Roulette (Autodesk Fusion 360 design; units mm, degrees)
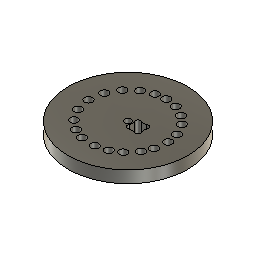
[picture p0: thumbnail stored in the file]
parameter "Diam" = 150
parameter "Length_Z" = 15
parameter "Diameter" = 10
parameter "Higth" = 15
parameter "Ss" = 15 (= "Diameter * 1.5")
parameter "Circumcircle_R" = 47.9434 (= "Ss / ( 2 * sin(( 180 / n ) * 1 deg) )")
parameter "HLZ" = 7.5 (= "Length_Z / 2")
parameter "Middle_Bar_Diam" = 8
sketch "Sketch1" plane through (0, 0, 0) normal (0, 0, 1) x axis (1, 0, 0)
  circle C1 centre (0, 0) radius 75
  point P1 (0, 0)
  point P2 (0, 0)
  coincident P1 P2
  dimension "d3" diameter C1 = 150 (= "Diam")
extrude "Extrude1" new body sketch "Sketch1" along normal blind 15 (= "Length_Z")
sketch "Sketch1" plane through (0, 0, 0) normal (0, 0, 1) x axis (1, 0, 0)
  circle C1 centre (0, 47.9434) radius 5
  point P1 (0, 0)
  point P2 (0, 47.9434)
  vertical P1 P2
  dimension "d7_1" diameter C1 = 10 (= "Diameter")
  dimension "d12" distance P1 P2 = 47.9434 (= "Circumcircle_R")
extrude "Extrude1" new body sketch "Sketch1" along normal blind 15 (= "Higth")
circular_pattern "C-Pattern1" TotalAngle 360 named "d4_1"
sketch "Sketch2" plane through (0, 0, 0) normal (0, 0, 1) x axis (1, 0, 0)
  circle C1 centre (0, 0) radius 5
  point P1 (0, 0)
  point P2 (0, 0)
  coincident P1 P2
  dimension "d13" diameter C1 = 10 (= "Diameter")
extrude "Extrude2" new body sketch "Sketch2" along normal blind 15 (= "Higth")
joint "Assemble1" alignAngle 0 alignOffsetX 0 alignOffsetY 0
combine "Combine2"
copy_paste "CopyPaste1"
combine "Combine3"
copy_paste "CopyPaste2"
combine "Combine4"
copy_paste "CopyPaste3"
combine "Combine5"
copy_paste "CopyPaste4"
combine "Combine6"
copy_paste "CopyPaste5"
combine "Combine7"
copy_paste "CopyPaste6"
combine "Combine8"
copy_paste "CopyPaste7"
combine "Combine9"
copy_paste "CopyPaste8"
combine "Combine10"
copy_paste "CopyPaste9"
combine "Combine11"
copy_paste "CopyPaste10"
combine "Combine12"
copy_paste "CopyPaste11"
combine "Combine13"
copy_paste "CopyPaste12"
combine "Combine14"
copy_paste "CopyPaste13"
combine "Combine15"
copy_paste "CopyPaste14"
combine "Combine16"
copy_paste "CopyPaste15"
combine "Combine17"
copy_paste "CopyPaste16"
combine "Combine18"
copy_paste "CopyPaste17"
combine "Combine19"
copy_paste "CopyPaste18"
combine "Combine20"
copy_paste "CopyPaste19"
combine "Combine21"
sketch "Sketch2" plane through (0, 0, 15) normal (0, 0, 1) x axis (-1, 0, 0)
  line L1 (-20, -7.5) -> (-5, -7.5)
  line L2 (-20, 7.5) -> (-20, -7.5)
  line L3 (-5, 7.5) -> (-20, 7.5)
  line L4 (-5, -7.5) -> (-5, 7.5)
  circle C1 centre (-27.4992, -39.2729) radius 5
  circle C2 centre (-14.0173, -45.8485) radius 5
  circle C3 centre (-37.259, -30.1718) radius 5
  circle C4 centre (-45.0521, -16.3976) radius 5
  circle C5 centre (-47.8777, -2.5092) radius 5
  circle C6 centre (-46.0862, 13.215) radius 5
  circle C7 centre (-41.0955, 24.6927) radius 5
  circle C8 centre (-30.8174, 36.7268) radius 5
  circle C9 centre (-19.5003, 43.7985) radius 5
  circle C10 centre (-5.8428, 47.586) radius 5
  circle C11 centre (10.7849, 46.7146) radius 5
  circle C12 centre (23.2434, 41.9322) radius 5
  circle C13 centre (35.0636, 32.6973) radius 5
  circle C14 centre (44.1321, 18.733) radius 5
  circle C15 centre (47.9142, 1.6732) radius 5
  circle C16 centre (45.3314, -15.6088) radius 5
  circle C17 centre (37.259, -30.1718) radius 5
  circle C18 centre (25.4061, -40.6583) radius 5
  circle C19 centre (12.4087, -46.3098) radius 5
  circle C20 centre (0, -47.9434) radius 5
  circle C21 centre (0, 0) radius 75
  circle C22 centre (0, 0) radius 4
  point P1 (0, 0)
  point P23 (0, 0)
  point P24 (-5, -7.5)
  point P25 (-20, -7.5)
  point P26 (-20, 7.5)
  coincident P1 P23
  horizontal L1
  vertical L2
  horizontal L3
  vertical L4
  dimension "d16" distance P24 P25 = 15 (= "Length_Z")
  dimension "d17" distance P25 P26 = 15 (= "Length_Z")
  dimension "d20" diameter C22 = 8 (= "Middle_Bar_Diam")
  dimension "d21" distance P1 L1 = 7.5 (= "HLZ")
extrude "Extrude2" cut sketch "Sketch2" profile of C22 L1 L2 L3 L4 distance 15 (= "Length_Z")
base_feature "Base Feature" bodies "dogboneTool"
combine "Combine22" bodies "dogboneTool"
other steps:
joint_origin "JointOrigin1"
create_component "CreateComponent1"
remove_body "RemoveBody1"
remove_body "RemoveBody2"
remove_body "RemoveBody3"
remove_body "RemoveBody4"
remove_body "RemoveBody5"
remove_body "RemoveBody6"
remove_body "RemoveBody7"
remove_body "RemoveBody8"
remove_body "RemoveBody9"
remove_body "RemoveBody10"
remove_body "RemoveBody11"
remove_body "RemoveBody12"
remove_body "RemoveBody13"
remove_body "RemoveBody14"
remove_body "RemoveBody15"
remove_body "RemoveBody16"
remove_body "RemoveBody17"
remove_body "RemoveBody18"
remove_body "RemoveBody19"
named bodies: "dogboneTool"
